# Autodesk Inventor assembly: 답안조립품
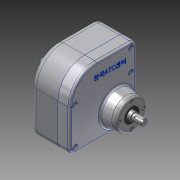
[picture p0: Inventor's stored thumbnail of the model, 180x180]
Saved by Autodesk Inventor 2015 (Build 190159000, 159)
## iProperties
Created: 2015-10
Part Number: 답안조립품
Document SubType Name: Assembly
Designer: youjin20
Author: youjin20
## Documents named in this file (13)
- C:\Users\youjin20\Desktop\451019V1002\답안조립품.iam
- C:\Users\youjin20\Desktop\451019V1002\본체.ipt
- C:\Users\youjin20\Desktop\451019V1002\앞커버.ipt
- C:\Users\youjin20\Desktop\451019V1002\M4 x 0.7.ipt
- C:\Users\youjin20\Desktop\451019V1002\오일실 12 x 22.ipt
- C:\Users\youjin20\Desktop\451019V1002\베어링 6001.ipt
- C:\Users\youjin20\Desktop\451019V1002\축 커버.ipt
- C:\Users\youjin20\Desktop\451019V1002\M3 x 0.5.ipt
- C:\Users\youjin20\Desktop\451019V1002\로드 축.ipt
- C:\Users\youjin20\Desktop\451019V1002\오일실 15 x 25.ipt
- C:\Users\youjin20\Desktop\451019V1002\베어링 6002.ipt
- C:\Users\youjin20\Desktop\451019V1002\편심 축.ipt
- C:\Users\youjin20\Desktop\451019V1002\로드.ipt
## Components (9 placed, 2 different names)
1. M4 x 0.7:1 — Insert:2
2. M4 x 0.7:2 — Insert:5
3. M4 x 0.7:3 — Insert:3
4. M4 x 0.7:4 — Insert:4
5. M4 x 0.7:5 — Insert:1
6. M3 x 0.5:1 — Insert:6
7. M3 x 0.5:2
8. M3 x 0.5:3
9. M3 x 0.5:4
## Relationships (6: Insert 6)
- Insert:1: M4 x 0.7:5
- Insert:2: M4 x 0.7:1
- Insert:3: M4 x 0.7:3
- Insert:4: M4 x 0.7:4
- Insert:5: M4 x 0.7:2
- Insert:6: M3 x 0.5:1
